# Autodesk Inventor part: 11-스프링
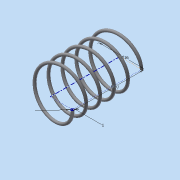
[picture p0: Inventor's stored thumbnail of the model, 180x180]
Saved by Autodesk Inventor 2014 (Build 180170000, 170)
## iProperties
Created: 2015-06
Part Number: 11-스프링
Material: 강철, 연강
Document SubType Name: Modeling
Designer: MYHOME
Density: 7.86 g/cm^3
Appearance: 강철
Mass: 1.53479 g
Surface Area: 7.89194 cm^2
Volume: 0.195266 cm^3
Author: MYHOME
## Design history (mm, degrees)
sketch "스케치1"
  geometry: L1 (0, 0)-(8, 0); L2 (8, 0)-(8, 21.5); L3 (8, 21.5)-(0, 21.5); L4 (0, 21.5)-(0, 0); C1 r 0.5 at (8, 0)
  constraints: 8 end point, 2 parallel, 1 centre point, 1 coincident, 1 horizontal, 1 perpendicular
  dimensions: "d0" = 1 diameter of C1; "d1" = 16 diameter of L2 L4; "d2" = 21.5 distance of L1.end L2.end (derived)
feature "코일1" sketch "스케치1" pitch "d3" = 10; turns "d5" = 5; dims "d4" = 21.5 (= d2), "d6" = 0, angle "d7" = 90 deg, angle "d8" = 90 deg, "d9" = 0, "d10" = 0
sketch "스케치2"
  geometry: L1 (-8.5, 0)-(-7.5, 0) reference; 1 further point
  constraints: 1 horizontal alignment
extrude "돌출1" cut sketch "스케치2" stored distance "d11" = 10; taper "d12" = 0 deg
node "작업 평면1"
sketch "스케치3"
  geometry: L1 (-7.5, 0)-(-8.5, 0) reference; 1 further point
  constraints: 1 horizontal alignment
extrude "돌출2" cut sketch "스케치3" stored distance "d14" = 10; taper "d15" = 0 deg
node "솔리드1"
node "절단 모서리 투영1"
node "절단 모서리 투영2"
other parameters: "d13" = 21.5 (= d2)
